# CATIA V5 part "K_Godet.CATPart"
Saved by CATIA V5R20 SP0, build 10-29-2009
Part number: Godet
Bounding box of the stored display mesh (mm): x -21 to 21, y 67.592 to 252.681, z 88.036 to 159.045
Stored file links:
  G:\Khaled_CFAO_2011\ST2M\ST2M_GR1\hgrenier\Khaled\CAD_ThinkMOTION\K_Godet.CATPart
  C:\Users\Tom\Documents\Cours 2A\CFAO\Projet thinkmotion\Hugo\porte_outil.CATProduct
  G:\Khaled_CFAO_2011\ST2M\ST2M_GR1\hgrenier\Khaled\CAD_ThinkMOTION\K_Bras.CATPart
  G:\Khaled_CFAO_2011\ST2M\ST2M_GR1\hgrenier\Khaled\CAD_ThinkMOTION\K_Bielette.CATPart
  G:\Khaled_CFAO_2011\ST2M\ST2M_GR1\hgrenier\Khaled\CAD_ThinkMOTION\K_Squelette.CATPart
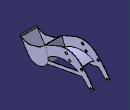
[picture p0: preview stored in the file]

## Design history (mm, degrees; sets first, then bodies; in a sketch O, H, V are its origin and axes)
External parameters (linked from other documents)
  External.diametre_trou_bras_godet = 6 mm
  External.Rayon = 2.1195 mm
  External.Rayon.1 = 3 mm
  External.Rayon.2 = 3 mm
Set1
  Plane1 "Plan_godet": linked copy from another document
  Plane2 "plan_sym": linked copy from another document
  Point1 "Centre_bras/godet": linked copy from another document
  Point2 "Centre_bielette/godet": linked copy from another document
  Point3 "Centre_godet/bielette2": linked copy from another document
  Point4 "Centre_godet/verin2": linked copy from another document
  Plane3 "Plan_bielle2": linked copy from another document
Body1 (main body)
  Sketch1 on Plane1, origin (21, 0, 0), H (0, 1, 0), V (0, 0, 1)
    point P1 (91.9303, 95.5047)
    line L1 (91.9303, 95.5047) -> (67.5921, 131.2689)
    line L2 (67.5921, 131.2689) -> (69.4673, 130.2462)
    line L3 (69.4673, 130.2462) -> (70.7441, 128.37)
    point P4 (70.7441, 128.37)
    spline S1 through (70.7441, 128.37) (75.6474, 125.6998) (86.8869, 122.6688) (96.9751, 123.3962) (100.8965, 124.4874) (115.9531, 129.0339) (124.163, 134.3381) (129.6705, 140.0381)
    line L4 (129.6705, 140.0381) -> (163.8118, 155.0266)
    point P5 (163.8118, 155.0266)
    point P6 (129.6705, 140.0381)
    spline S2 through (163.8118, 155.0266) (170.2773, 157.3143) (178.5564, 158.8131) (193.151, 158.1744) (206.2833, 153.8548) (224.1095, 140.4011) (237.6015, 125.7775) (252.681, 104.6295)
    spline S3 through (252.681, 104.6295) (252.2312, 102.9647) (251.0169, 101.6598) (246.7894, 98.6901) (245.0804, 97.6102)
    spline S4 through (245.0804, 97.6102) (242.1122, 100.13) (235.7709, 106.9243) (223.1783, 119.0281) (194.3308, 131.9869) (166.8969, 131.5369) (139.0922, 118.1717)
    spline S5 through (139.0922, 118.1717) (137.927, 107.9309) (130.7437, 95.9256) (112.867, 88.0854) (98.5004, 90.9438) (91.9303, 95.5047)
    point P7 (70.7441, 128.37)
    point P8 (129.6705, 140.0381)
    point P9 (163.8118, 155.0266)
    point P10 (252.681, 104.6295)
    point P11 (252.681, 104.6295)
    point P12 (245.0804, 97.6102)
    point P13 (245.0804, 97.6102)
    point P14 (139.0922, 118.1717)
    point P15 (139.0922, 118.1717)
    point P16 (91.9303, 95.5047)
    parallelism: L3 L1
    coincidence: P7 P4, P8 P6, P9 P5, P10 P11, P12 P13, P14 P15, P16 P1
  Pad1: profile Sketch1, direction (-1, 0, 0), up to Plane2
  Shell1: IntOffset 1, Face (end face of Pad1; face of Pad1 from Sketch1.S2; face of Pad1 from Sketch1.S3; face of Pad1 from Sketch1.L4; face of Pad1 from Sketch1.S1), ExtOffset 0
  Sketch2 on start face of Pad1, origin (21, 0, 0), H (0, 1, 0), V (0, 0, 1)
    circle A1 centre (184.534, 150.027) radius 3
    point P1 (184.534, 150.027)
    circle A2 centre (193.142, 137.987) radius 3
    point P2 (193.142, 137.987)
    reference projected point E1 (184.534, 150.027) from Point1
    reference projected point E2 (193.142, 137.987) from Point2
    circle A3 centre (223.049, 133.683) radius 3
    point P3 (223.049, 133.683)
    circle A4 centre (246.47, 103.773) radius 2.5697
    point P4 (246.47, 103.773)
    reference projected point E3 (246.47, 103.773) from Point3
    reference projected point E4 (223.049, 133.683) from Point4
    radius A2 = 3 {= External.Rayon.1}
    radius A1 = 3 {= External.Rayon.2}
    radius A3 = 3
    radius A4 = 2.5697
    coincidence: P1 E1, P2 E2, P4 E3, P3 E4
  Pocket1: profile Sketch2, direction (-1, 0, 0), through (limit type 6)
  Sketch3 on Plane3, origin (15, 0, 0), H (0, 1, 0), V (0, 0, 1)
    line L1 (211.0545, 134.1559) -> (258.019, 134.1559)
    line L2 (258.019, 134.1559) -> (258.019, 91.9561)
    line L3 (258.019, 91.9561) -> (211.0545, 91.9561)
    line L4 (211.0545, 91.9561) -> (211.0545, 134.1559)
    horizontal: L1 H, L3 H
    vertical: L2 V, L4 V
  Pocket2: profile Sketch3, direction (-1, 0, 0), through (limit type 6), opposite side length 5
  Sketch4 on face of Pocket2, origin (20, 0, 0), H (0, -1, 0), V (0, 0, 1)
    point P1 (-129.6705, 140.0381)
    line L1 (-129.6705, 140.0381) -> (-138.0583, 118.6283)
    point P2 (-138.0583, 118.6283)
    line L2 (-138.0583, 118.6283) -> (-140.3694, 120.4029)
    point P3 (-140.3694, 120.4029)
    line L3 (-140.3694, 120.4029) -> (-132.4382, 141.2531)
    point P4 (-132.4382, 141.2531)
    line L4 (-132.4382, 141.2531) -> (-129.6705, 140.0381)
    reference projected point E1 (-129.6705, 140.0381) from vertex [face of Pad1 from Sketch1.L4 | face of Shell1 | face of Pad1 from Sketch1.S1]
    reference projected point E2 (-138.0583, 118.6283) from vertex [face of Shell1 | face of Shell1 | end face of Pad1]
    reference projected line E3 (-163.8118, 155.0266) -> (-129.6705, 140.0381) from edge [face of Shell1 | face of Pad1 from Sketch1.L4]
    reference projected curve E4 from edge [face of Shell1 | end face of Pad1]
    distance P4 E3 = 0
    distance P3 E4 = 0
    coincidence: P1 E1, P2 E2
  Pad2: profile Sketch4, direction (-1, 0, 0), up to Plane2
  Sketch5 on Plane1, origin (21, 0, 0), H (0, 1, 0), V (0, 0, 1)
    line L1 (138.6929, 111.1278) -> (213.5208, 125.173)
    point P1 (138.6929, 111.1278)
    point P2 (213.5208, 125.173)
    reference projected curve E1 from edge [face of Pad1 | start face of Pad1]
    reference projected curve E2 from edge [face of Pad1 | start face of Pad1]
    line L2 (223.1674, 119.0362) -> (135.7328, 102.6247)
    point P3 (223.1674, 119.0362)
    point P4 (135.7328, 102.6247)
    reference projected curve E3 from edge [face of Pocket2 | face of Pad1]
    reference projected curve E4 from edge [face of Pad1 | start face of Pad1]
    spline S1 through (138.6929, 111.1278) (138.2118, 108.9438) (136.7127, 104.638) (135.7328, 102.6247)
    reference projected curve E5 from edge [face of Pad1 | start face of Pad1]
    reference projected curve E6 from edge [face of Pad1 | start face of Pad1]
    spline S2 through (213.5208, 125.173) (217.4348, 122.9403) (220.8638, 120.7036) (223.1674, 119.0362)
    reference projected curve E7 from edge [face of Pad1 | start face of Pad1]
    reference projected curve E8 from edge [face of Pad1 | start face of Pad1]
    point P5 (138.6929, 111.1278)
    point P6 (135.7328, 102.6247)
    point P7 (138.2118, 108.9438)
    point P8 (136.7127, 104.638)
    point P9 (213.5208, 125.173)
    point P10 (223.1674, 119.0362)
    point P11 (220.8638, 120.7036)
    point P12 (217.4348, 122.9403)
    distance P2 E1 = 0
    distance E2 P1 = 0
    distance P3 E3 = 0
    distance P4 E4 = 0
    distance P7 E5 = 0
    distance P8 E6 = 0
    distance P11 E7 = 0
    distance P12 E8 = 0
    parallelism: L2 L1
    coincidence: P5 P1, P6 P4, P9 P2, P10 P3
  Pad3: profile Sketch5, direction (-1, 0, 0), length 1
  Mirror1: of the body so far, about Plane2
